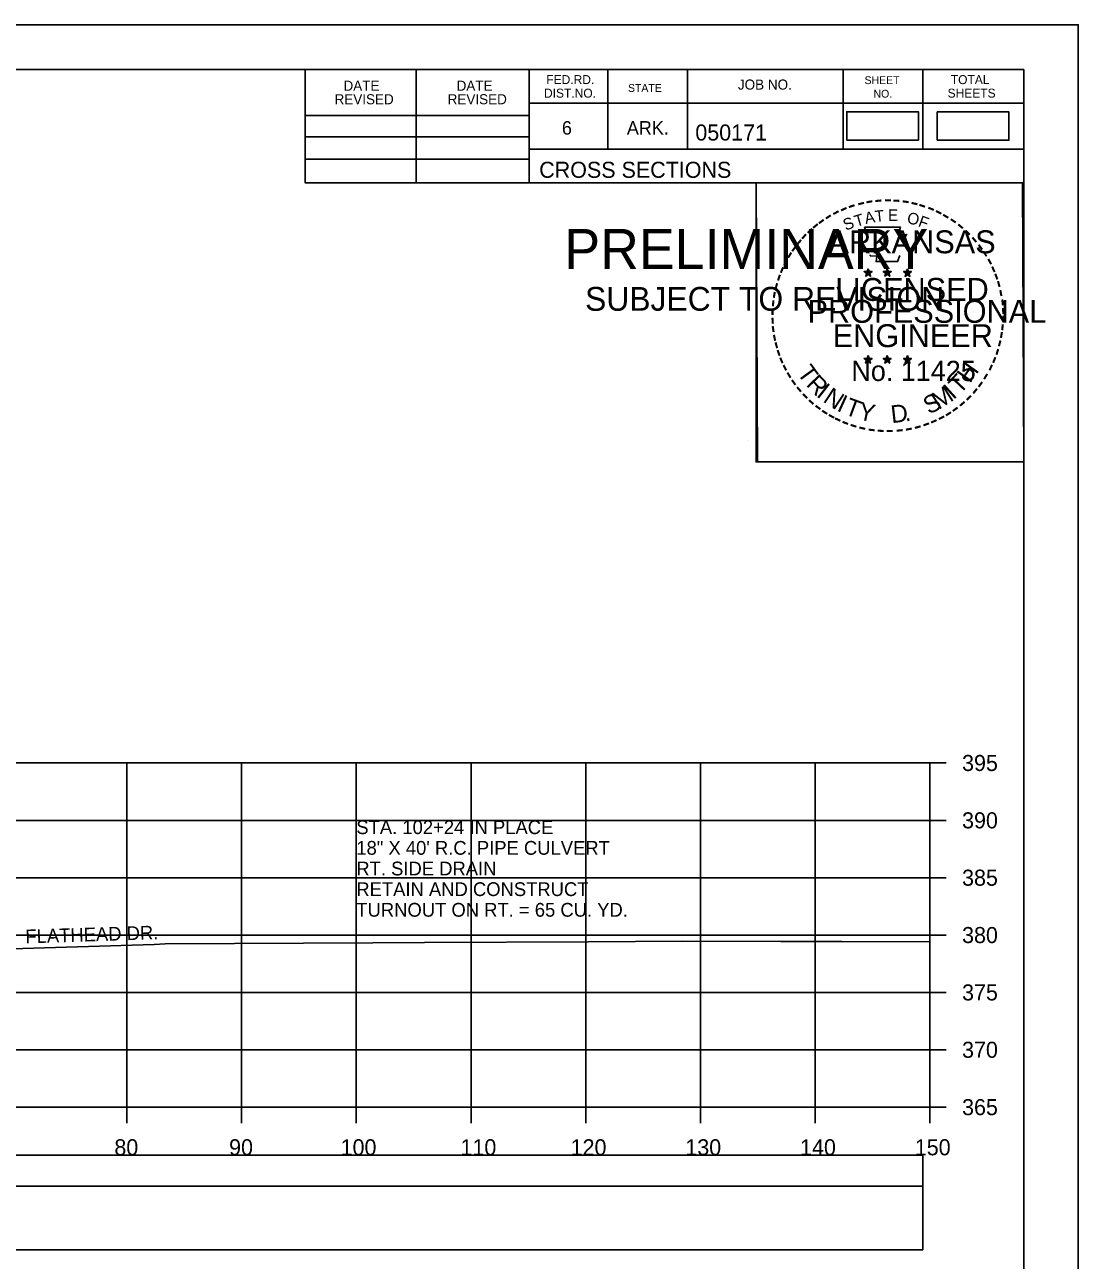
# Model space of a CAD drawing. Extents: x -37291014 to -37290680, y -936053 to -933067.
# Drawn here: x -37290772 to -37290680.2, y -935521 to -935413.3 of the extents above; entities that cross this region are included whole.
import ezdxf

# ---------------------------------------------------------------- set-up
doc = ezdxf.new("R2010")
doc.units = 0
for name, color, linetype in [('Default', 7, 'Continuous'), ('R_Axis', 7, 'Continuous'), ('R_Axis Annot', 7, 'Continuous'), ('R_Border', 7, 'Continuous'), ('R_Border PE', 7, 'Continuous'), ('R_Border Prem', 7, 'Continuous'), ('R_Exist Surface', 7, 'Continuous'), ('R_Grid', 7, 'Continuous'), ('R_No Plot', 7, 'Continuous'), ('R_Water Annot', 7, 'Continuous'), ('R_Xsect Elev', 7, 'Continuous')]:
    doc.layers.add(name, color=color, linetype=linetype)

msp = doc.modelspace()

# ---------------------------------------------------------------- linework, layer by layer
at = {"layer": 'Default'}
for points in [[(-37290700.35, -935423.36), (-37290694.1, -935423.36), (-37290694.1, -935420.88), (-37290700.35, -935420.88)], [(-37290692.46, -935423.36), (-37290686.21, -935423.36), (-37290686.21, -935420.89), (-37290692.46, -935420.89)], [(-37290992.48, -935514.55), (-37290693.72, -935514.55), (-37290693.72, -935511.85), (-37290992.48, -935511.85)], [(-37290992.48, -935520.08), (-37290693.72, -935520.08), (-37290693.72, -935514.55), (-37290992.48, -935514.55)]]:
    msp.add_lwpolyline(points, close=True, dxfattribs=at)
at = {"layer": 'R_Axis'}
for p, q in [((-37290693.1, -935507.65), (-37290693.1, -935477.65)), ((-37290691.7, -935477.65), (-37290693.1, -935477.65)), ((-37290691.7, -935482.65), (-37290693.1, -935482.65)), ((-37290691.7, -935487.65), (-37290693.1, -935487.65)), ((-37290691.7, -935492.65), (-37290693.1, -935492.65)), ((-37290691.7, -935497.65), (-37290693.1, -935497.65)), ((-37290691.7, -935502.65), (-37290693.1, -935502.65)), ((-37290993.1, -935507.65), (-37290693.1, -935507.65)), ((-37290763.1, -935509.05), (-37290763.1, -935507.65)), ((-37290753.1, -935509.05), (-37290753.1, -935507.65)), ((-37290743.1, -935509.05), (-37290743.1, -935507.65)), ((-37290733.1, -935509.05), (-37290733.1, -935507.65)), ((-37290723.1, -935509.05), (-37290723.1, -935507.65)), ((-37290713.1, -935509.05), (-37290713.1, -935507.65)), ((-37290703.1, -935509.05), (-37290703.1, -935507.65)), ((-37290693.1, -935509.05), (-37290693.1, -935507.65)), ((-37290691.7, -935507.65), (-37290693.1, -935507.65))]:
    msp.add_line(p, q, dxfattribs=at)
at = {"layer": 'R_Border'}
for p, q in [((-37291001.1, -935417.19), (-37290684.92, -935417.19)), ((-37290747.56, -935427.07), (-37290747.56, -935417.19)), ((-37290737.88, -935427.07), (-37290737.88, -935417.19)), ((-37290728.02, -935417.19), (-37290728.02, -935427.07)), ((-37290721.18, -935417.19), (-37290721.18, -935424.13)), ((-37290714.24, -935417.19), (-37290714.24, -935424.13)), ((-37290700.66, -935417.19), (-37290700.66, -935424.13)), ((-37290693.72, -935417.19), (-37290693.72, -935424.13)), ((-37290684.92, -935622.65), (-37290684.92, -935417.19)), ((-37290684.92, -935420.13), (-37290728.02, -935420.13)), ((-37290684.92, -935420.11), (-37290684.92, -935420.11)), ((-37290747.56, -935421.21), (-37290728.02, -935421.21)), ((-37290747.56, -935423.07), (-37290728.02, -935423.07)), ((-37290684.92, -935424.13), (-37290728.02, -935424.13)), ((-37290725.06, -935424.13), (-37290684.92, -935424.13)), ((-37290747.56, -935425.01), (-37290728.02, -935425.01)), ((-37290684.92, -935427.07), (-37290747.56, -935427.07))]:
    msp.add_line(p, q, dxfattribs=at)
at = {"layer": 'R_Border PE'}
for p, q in [((-37290698.84, -935434.81), (-37290698.49, -935434.92)), ((-37290698.84, -935434.81), (-37290698.58, -935434.86)), ((-37290698.84, -935434.81), (-37290698.6, -935434.93)), ((-37290698.7, -935435.22), (-37290698.49, -935434.92)), ((-37290698.7, -935435.22), (-37290698.58, -935434.98)), ((-37290698.49, -935434.56), (-37290698.53, -935434.81)), ((-37290698.49, -935434.92), (-37290698.49, -935434.56)), ((-37290698.49, -935434.56), (-37290698.44, -935434.81)), ((-37290698.14, -935434.81), (-37290698.49, -935434.92)), ((-37290698.27, -935435.22), (-37290698.49, -935434.92)), ((-37290698.14, -935434.81), (-37290698.43, -935434.86)), ((-37290698.27, -935435.22), (-37290698.41, -935434.93)), ((-37290698.14, -935434.81), (-37290698.34, -935434.91)), ((-37290697.17, -935434.81), (-37290696.82, -935434.92)), ((-37290697.17, -935434.81), (-37290696.91, -935434.86)), ((-37290697.17, -935434.81), (-37290696.93, -935434.93)), ((-37290697.03, -935435.22), (-37290696.82, -935434.92)), ((-37290697.03, -935435.22), (-37290696.91, -935434.98)), ((-37290696.82, -935434.56), (-37290696.86, -935434.81)), ((-37290696.82, -935434.92), (-37290696.82, -935434.56)), ((-37290696.82, -935434.56), (-37290696.77, -935434.81)), ((-37290696.47, -935434.81), (-37290696.82, -935434.92)), ((-37290696.6, -935435.22), (-37290696.82, -935434.92)), ((-37290696.47, -935434.81), (-37290696.76, -935434.86)), ((-37290696.6, -935435.22), (-37290696.74, -935434.93)), ((-37290696.47, -935434.81), (-37290696.67, -935434.91)), ((-37290695.4, -935434.82), (-37290695.05, -935434.94)), ((-37290695.4, -935434.82), (-37290695.15, -935434.87)), ((-37290695.4, -935434.82), (-37290695.17, -935434.95)), ((-37290695.27, -935435.23), (-37290695.05, -935434.94)), ((-37290695.27, -935435.23), (-37290695.14, -935434.99)), ((-37290695.05, -935434.57), (-37290695.09, -935434.82)), ((-37290695.05, -935434.94), (-37290695.05, -935434.57)), ((-37290695.05, -935434.57), (-37290695, -935434.82)), ((-37290694.71, -935434.82), (-37290695.05, -935434.94)), ((-37290694.84, -935435.23), (-37290695.05, -935434.94)), ((-37290694.71, -935434.82), (-37290694.99, -935434.87)), ((-37290694.84, -935435.23), (-37290694.98, -935434.94)), ((-37290694.71, -935434.82), (-37290694.91, -935434.93)), ((-37290698.7, -935435.22), (-37290698.49, -935435)), ((-37290698.27, -935435.22), (-37290698.49, -935435.01)), ((-37290697.03, -935435.22), (-37290696.82, -935435)), ((-37290696.6, -935435.22), (-37290696.82, -935435.01)), ((-37290695.27, -935435.23), (-37290695.06, -935435.02)), ((-37290694.84, -935435.23), (-37290695.06, -935435.02)), ((-37290698.84, -935442.39), (-37290698.49, -935442.5)), ((-37290698.84, -935442.39), (-37290698.59, -935442.43)), ((-37290698.84, -935442.39), (-37290698.6, -935442.51)), ((-37290698.71, -935442.79), (-37290698.49, -935442.5)), ((-37290698.49, -935442.13), (-37290698.53, -935442.38)), ((-37290698.49, -935442.5), (-37290698.49, -935442.13)), ((-37290698.49, -935442.13), (-37290698.44, -935442.38)), ((-37290698.14, -935442.39), (-37290698.49, -935442.5)), ((-37290698.28, -935442.79), (-37290698.49, -935442.5)), ((-37290698.14, -935442.39), (-37290698.43, -935442.43)), ((-37290698.28, -935442.79), (-37290698.42, -935442.5)), ((-37290698.14, -935442.39), (-37290698.35, -935442.49)), ((-37290697.17, -935442.39), (-37290696.82, -935442.5)), ((-37290697.17, -935442.39), (-37290696.92, -935442.43)), ((-37290697.17, -935442.39), (-37290696.93, -935442.51)), ((-37290697.04, -935442.79), (-37290696.82, -935442.5)), ((-37290696.82, -935442.13), (-37290696.86, -935442.38)), ((-37290696.82, -935442.5), (-37290696.82, -935442.13)), ((-37290696.82, -935442.13), (-37290696.77, -935442.38)), ((-37290696.48, -935442.39), (-37290696.82, -935442.5)), ((-37290696.61, -935442.79), (-37290696.82, -935442.5)), ((-37290696.48, -935442.39), (-37290696.76, -935442.43)), ((-37290696.61, -935442.79), (-37290696.75, -935442.5)), ((-37290696.48, -935442.39), (-37290696.68, -935442.49)), ((-37290695.4, -935442.4), (-37290695.06, -935442.51)), ((-37290695.4, -935442.4), (-37290695.15, -935442.44)), ((-37290695.4, -935442.4), (-37290695.17, -935442.52)), ((-37290695.27, -935442.8), (-37290695.06, -935442.51)), ((-37290695.06, -935442.14), (-37290695.1, -935442.39)), ((-37290695.06, -935442.51), (-37290695.06, -935442.14)), ((-37290695.06, -935442.14), (-37290695.01, -935442.39)), ((-37290694.71, -935442.4), (-37290695.06, -935442.51)), ((-37290694.84, -935442.8), (-37290695.06, -935442.51)), ((-37290694.71, -935442.4), (-37290694.99, -935442.44)), ((-37290694.84, -935442.8), (-37290694.98, -935442.51)), ((-37290694.71, -935442.4), (-37290694.91, -935442.5)), ((-37290698.71, -935442.79), (-37290698.58, -935442.55)), ((-37290698.71, -935442.79), (-37290698.49, -935442.58)), ((-37290698.28, -935442.79), (-37290698.49, -935442.58)), ((-37290697.04, -935442.79), (-37290696.91, -935442.55)), ((-37290697.04, -935442.79), (-37290696.82, -935442.58)), ((-37290696.61, -935442.79), (-37290696.82, -935442.58)), ((-37290695.27, -935442.8), (-37290695.15, -935442.56)), ((-37290695.27, -935442.8), (-37290695.06, -935442.59)), ((-37290694.84, -935442.8), (-37290695.06, -935442.59))]:
    msp.add_line(p, q, dxfattribs=at)
for points in [[(-37290698.8, -935430.93), (-37290698.53, -935431.76)], [(-37290695.28, -935431.86), (-37290695.14, -935431.57), (-37290695.83, -935431.6), (-37290695.68, -935430.93), (-37290698.8, -935430.93)], [(-37290698.3, -935433.36), (-37290698.3, -935433.44), (-37290697.74, -935433.46), (-37290697.79, -935433.94), (-37290695.92, -935433.94), (-37290695.72, -935433.4)], [(-37290698.49, -935434.56), (-37290698.27, -935435.22), (-37290698.84, -935434.81), (-37290698.14, -935434.81), (-37290698.7, -935435.22), (-37290698.49, -935434.56)], [(-37290696.82, -935434.56), (-37290696.6, -935435.22), (-37290697.17, -935434.81), (-37290696.47, -935434.81), (-37290697.03, -935435.22), (-37290696.82, -935434.56)], [(-37290695.05, -935434.57), (-37290694.84, -935435.23), (-37290695.4, -935434.82), (-37290694.71, -935434.82), (-37290695.27, -935435.23), (-37290695.05, -935434.57)], [(-37290698.49, -935442.13), (-37290698.28, -935442.79), (-37290698.84, -935442.39), (-37290698.14, -935442.39), (-37290698.71, -935442.79), (-37290698.49, -935442.13)], [(-37290696.82, -935442.13), (-37290696.61, -935442.79), (-37290697.17, -935442.39), (-37290696.48, -935442.39), (-37290697.04, -935442.79), (-37290696.82, -935442.13)], [(-37290695.06, -935442.14), (-37290694.84, -935442.8), (-37290695.4, -935442.4), (-37290694.71, -935442.4), (-37290695.27, -935442.8), (-37290695.06, -935442.14)]]:
    msp.add_lwpolyline(points, dxfattribs=at)
for centre, radius in [((-37290698.49, -935434.92), 0.172), ((-37290698.49, -935434.92), 0.145), ((-37290698.49, -935434.92), 0.116), ((-37290698.49, -935434.92), 0.0991), ((-37290698.49, -935434.92), 0.0747), ((-37290698.49, -935434.92), 0.0495), ((-37290698.49, -935434.92), 0.0296), ((-37290696.82, -935434.92), 0.172), ((-37290696.82, -935434.92), 0.145), ((-37290696.82, -935434.92), 0.116), ((-37290696.82, -935434.92), 0.0991), ((-37290696.82, -935434.92), 0.0747), ((-37290696.82, -935434.92), 0.0495), ((-37290696.82, -935434.92), 0.0296), ((-37290695.05, -935434.94), 0.172), ((-37290695.05, -935434.94), 0.145), ((-37290695.05, -935434.94), 0.116), ((-37290695.05, -935434.94), 0.0991), ((-37290695.05, -935434.94), 0.0747), ((-37290695.05, -935434.94), 0.0495), ((-37290695.05, -935434.94), 0.0296), ((-37290698.49, -935442.5), 0.172), ((-37290698.49, -935442.5), 0.145), ((-37290698.49, -935442.5), 0.116), ((-37290698.49, -935442.5), 0.0991), ((-37290698.49, -935442.5), 0.0747), ((-37290698.49, -935442.5), 0.0495), ((-37290698.49, -935442.5), 0.0296), ((-37290696.82, -935442.5), 0.172), ((-37290696.82, -935442.5), 0.145), ((-37290696.82, -935442.5), 0.116), ((-37290696.82, -935442.5), 0.0991), ((-37290696.82, -935442.5), 0.0747), ((-37290696.82, -935442.5), 0.0495), ((-37290696.82, -935442.5), 0.0296), ((-37290695.06, -935442.51), 0.172), ((-37290695.06, -935442.51), 0.145), ((-37290695.06, -935442.51), 0.116), ((-37290695.06, -935442.51), 0.0991), ((-37290695.06, -935442.51), 0.0747), ((-37290695.06, -935442.51), 0.0495), ((-37290695.06, -935442.51), 0.0296)]:
    msp.add_circle(centre, radius, dxfattribs=at)
at = {"layer": 'R_Exist Surface'}
msp.add_lwpolyline([(-37290774.08, -935493.88), (-37290760.71, -935493.46), (-37290759.75, -935493.42), (-37290741.66, -935493.34), (-37290737.15, -935493.31), (-37290722.9, -935493.24), (-37290714.65, -935493.17), (-37290706.09, -935493.2), (-37290700.79, -935493.2), (-37290693.1, -935493.24)], dxfattribs=at)
at = {"layer": 'R_Grid'}
for p, q in [((-37290993.1, -935477.65), (-37290693.1, -935477.65)), ((-37290763.1, -935507.65), (-37290763.1, -935477.65)), ((-37290753.1, -935507.65), (-37290753.1, -935477.65)), ((-37290743.1, -935507.65), (-37290743.1, -935477.65)), ((-37290733.1, -935507.65), (-37290733.1, -935477.65)), ((-37290723.1, -935507.65), (-37290723.1, -935477.65)), ((-37290713.1, -935507.65), (-37290713.1, -935477.65)), ((-37290703.1, -935507.65), (-37290703.1, -935477.65)), ((-37290693.1, -935507.65), (-37290693.1, -935477.65)), ((-37290993.1, -935482.65), (-37290693.1, -935482.65)), ((-37290993.1, -935487.65), (-37290693.1, -935487.65)), ((-37290993.1, -935492.65), (-37290693.1, -935492.65)), ((-37290993.1, -935497.65), (-37290693.1, -935497.65)), ((-37290993.1, -935502.65), (-37290693.1, -935502.65)), ((-37290993.1, -935507.65), (-37290693.1, -935507.65))]:
    msp.add_line(p, q, dxfattribs=at)
at = {"layer": 'R_No Plot'}
for p, q in [((-37291013.5, -935413.29), (-37290680.17, -935413.29)), ((-37290708.89, -935449.52), (-37290708.89, -935449.52))]:
    msp.add_line(p, q, dxfattribs=at)
for points in [[(-37291013.51, -935413.29), (-37290680.17, -935413.29), (-37290680.17, -935626.63), (-37291013.51, -935626.63)], [(-37290767.18, -935417.19), (-37290747.56, -935417.19), (-37290747.56, -935427.07), (-37290731.45, -935427.07), (-37290708.25, -935427.07), (-37290708.25, -935451.4), (-37290684.92, -935451.4), (-37290684.92, -935622.65), (-37291001.1, -935622.65), (-37291001.1, -935417.19)], [(-37290708.25, -935427.07), (-37290685.04, -935427.07), (-37290684.92, -935451.4), (-37290708.13, -935451.4)]]:
    msp.add_lwpolyline(points, close=True, dxfattribs=at)

# ---------------------------------------------------------------- texts
at = {"layer": 'R_Axis Annot'}
for s, p in [('395', (-37290690.3, -935478.35)), ('390', (-37290690.3, -935483.35)), ('385', (-37290690.3, -935488.35)), ('380', (-37290690.3, -935493.35)), ('375', (-37290690.3, -935498.35)), ('370', (-37290690.3, -935503.35)), ('365', (-37290690.3, -935508.35)), ('80', (-37290764.19, -935511.85)), ('90', (-37290754.19, -935511.85)), ('100', (-37290744.47, -935511.85)), ('110', (-37290734.02, -935511.85)), ('120', (-37290724.42, -935511.85)), ('130', (-37290714.42, -935511.85)), ('140', (-37290704.42, -935511.85)), ('150', (-37290694.42, -935511.85))]:
    msp.add_text(s, height=1.4, dxfattribs=at).set_placement(p)
at = {"layer": 'R_Border'}
for s, height, p in [('FED.RD.', 0.782, (-37290726.54, -935418.47)), ('TOTAL', 0.782, (-37290691.28, -935418.47)), ('DATE', 0.879, (-37290744.22, -935419.05)), ('DATE', 0.879, (-37290734.36, -935419.05)), ('STATE', 0.684, (-37290719.42, -935419.15)), ('JOB NO.', 0.879, (-37290709.84, -935418.95)), ('SHEET', 0.684, (-37290698.8, -935418.47)), ('REVISED', 0.879, (-37290745, -935420.23)), ('REVISED', 0.879, (-37290735.14, -935420.23)), ('DIST.NO.', 0.782, (-37290726.74, -935419.65)), ('NO.', 0.684, (-37290698.02, -935419.65)), ('SHEETS', 0.782, (-37290691.56, -935419.65)), ('6', 1.17, (-37290725.18, -935422.87)), ('ARK.', 1.172, (-37290719.52, -935422.87)), ('050171', 1.4, (-37290713.55, -935423.39)), ('CROSS SECTIONS', 1.4, (-37290727.16, -935426.64))]:
    msp.add_text(s, height=height, dxfattribs=at).set_placement(p)
at = {"layer": 'R_Border PE'}
for s, height, rotation, p in [('-', 1.6, 5.8968, (-37290697.89, -935429.29)), ('-', 1.6, 0.1862, (-37290697.12, -935429.22)), ('-', 1.6, 357.743, (-37290696.4, -935429.24)), ('-', 1.6, 28.7918, (-37290701.31, -935430.39)), ('-', 1.6, 24.3072, (-37290700.68, -935430.08)), ('-', 1.6, 19.1761, (-37290700.05, -935429.81)), ('-', 1.6, 13.6302, (-37290699.3, -935429.57)), ('A', 1, 11.2132, (-37290698.7, -935430.67)), ('-', 1.6, 10.2193, (-37290698.62, -935429.4)), ('T', 1, 6.0228, (-37290697.85, -935430.51)), ('E', 1, 0.8323, (-37290696.75, -935430.4)), ('-', 1.6, 352.1617, (-37290695.65, -935429.29)), ('-', 1.6, 347.2049, (-37290694.93, -935429.41)), ('-', 1.6, 342.3362, (-37290694.3, -935429.56)), ('-', 1.6, 337.8551, (-37290693.56, -935429.78)), ('-', 1.6, 334.1211, (-37290692.93, -935430.05)), ('-', 1.6, 38.9507, (-37290702.97, -935431.54)), ('-', 1.6, 36.2317, (-37290702.49, -935431.16)), ('-', 1.6, 34.0636, (-37290701.91, -935430.76)), ('S', 1, 21.594, (-37290700.44, -935431.26)), ('T', 1, 16.4036, (-37290699.53, -935430.93)), ('O', 1, 350.4515, (-37290695.14, -935430.61)), ('F', 1, 340.0707, (-37290694.19, -935430.84)), ('-', 1.6, 329.6409, (-37290692.35, -935430.34)), ('-', 1.6, 325.8627, (-37290691.71, -935430.7)), ('-', 1.6, 320.5297, (-37290691.1, -935431.12)), ('-', 1.6, 48.4231, (-37290703.85, -935432.43)), ('-', 1.6, 42.9622, (-37290703.4, -935431.95)), ('-', 1.6, 315.5786, (-37290690.5, -935431.61)), ('-', 1.6, 54.2325, (-37290704.66, -935433.48)), ('-', 1.6, 50.6142, (-37290704.25, -935432.92)), ('-', 1.6, 309.8797, (-37290689.93, -935432.16)), ('-', 1.6, 306.6522, (-37290689.41, -935432.76)), ('-', 1.6, 62.8713, (-37290705.3, -935434.63)), ('-', 1.6, 58.0706, (-37290704.99, -935434.01)), ('-', 1.4, 303.6753, (-37290688.92, -935433.33)), ('-', 1.6, 299.6684, (-37290688.6, -935433.94)), ('-', 1.6, 67.7743, (-37290705.56, -935435.24)), ('-', 1.6, 294.6628, (-37290688.28, -935434.55)), ('-', 1.6, 290.5728, (-37290688.02, -935435.13)), ('-', 1.6, 75.461, (-37290705.98, -935436.58)), ('-', 1.6, 72.3945, (-37290705.78, -935435.87)), ('-', 1.6, 285.1233, (-37290687.79, -935435.71)), ('-', 1.6, 81.2013, (-37290706.11, -935437.29)), ('-', 1.6, 280.5493, (-37290687.59, -935436.45)), ('-', 1.6, 89.0622, (-37290706.21, -935438.69)), ('-', 1.6, 85.1863, (-37290706.18, -935437.98)), ('-', 1.6, 276.5962, (-37290687.42, -935437.22)), ('-', 1.6, 274.3301, (-37290687.36, -935437.94)), ('-', 1.6, 94.1959, (-37290706.17, -935439.41)), ('-', 1.6, 269.9407, (-37290687.33, -935438.57)), ('-', 1.6, 98.9479, (-37290706.1, -935440.08)), ('-', 1.6, 101.7149, (-37290705.97, -935440.81)), ('-', 1.6, 260.9953, (-37290687.42, -935439.89)), ('-', 1.6, 263.5172, (-37290687.35, -935439.24)), ('-', 1.6, 105.4578, (-37290705.8, -935441.41)), ('-', 1.6, 255.7626, (-37290687.53, -935440.57)), ('-', 1.6, 109.0874, (-37290705.59, -935442.04)), ('-', 1.6, 114.0643, (-37290705.34, -935442.63)), ('-', 1.6, 247.8887, (-37290687.93, -935441.96)), ('-', 1.6, 252.8681, (-37290687.71, -935441.29)), ('-', 1.6, 115.7289, (-37290705.03, -935443.25)), ('-', 1.6, 120.4471, (-37290704.67, -935443.84)), ('T', 1.54, 306.0406, (-37290704.73, -935443.66)), ('H', 1.54, 54.6088, (-37290689.61, -935444.62)), ('-', 1.6, 244.6197, (-37290688.2, -935442.59)), ('-', 1.6, 125.8934, (-37290704.27, -935444.4)), ('R', 1.54, 314.005, (-37290703.97, -935444.71)), ('I', 1.54, 321.9694, (-37290703.07, -935445.64)), ('I', 1.54, 42.1136, (-37290691.06, -935446.04)), ('T', 1.54, 46.6444, (-37290690.5, -935445.57)), ('-', 1.6, 233.8452, (-37290688.99, -935444)), ('-', 1.6, 239.0712, (-37290688.59, -935443.34)), ('-', 1.6, 130.7181, (-37290703.81, -935444.95)), ('-', 1.6, 134.2238, (-37290703.29, -935445.49)), ('N', 1.54, 326.5002, (-37290702.5, -935446.11)), ('I', 1.54, 335.3603, (-37290701.29, -935446.9)), ('S', 1.54, 26.9312, (-37290693.19, -935447.3)), ('M', 1.54, 32.6563, (-37290692.35, -935446.89)), ('-', 1.6, 225.7653, (-37290689.9, -935445.13)), ('-', 1.6, 231.2538, (-37290689.42, -935444.56)), ('-', 1.6, 138.9338, (-37290702.77, -935445.96)), ('-', 1.6, 144.6463, (-37290702.21, -935446.36)), ('T', 1.54, 339.8912, (-37290700.63, -935447.22)), ('Y', 1.54, 347.8556, (-37290699.42, -935447.67)), ('D', 1.54, 6.3969, (-37290696.43, -935448.03)), ('-', 1.6, 215.7363, (-37290690.97, -935446.11)), ('-', 1.6, 221.0851, (-37290690.42, -935445.64)), ('-', 1.6, 148.0898, (-37290701.65, -935446.74)), ('-', 1.6, 151.5704, (-37290701.07, -935447.06)), ('-', 1.6, 154.6002, (-37290700.55, -935447.31)), ('-', 1.6, 158.5612, (-37290699.92, -935447.56)), ('.', 1.54, 13.7642, (-37290695.24, -935447.9)), ('-', 1.6, 204.2516, (-37290692.69, -935447.16)), ('-', 1.6, 207.3568, (-37290692.06, -935446.84)), ('-', 1.6, 212.2491, (-37290691.51, -935446.5)), ('-', 1.6, 162.7983, (-37290699.24, -935447.77)), ('-', 1.6, 167.5555, (-37290698.52, -935447.94)), ('-', 1.6, 173.1155, (-37290697.75, -935448.05)), ('-', 1.6, 176.5183, (-37290697, -935448.1)), ('-', 1.6, 181.5918, (-37290696.26, -935448.08)), ('-', 1.6, 185.8167, (-37290695.45, -935448.01)), ('-', 1.6, 191.2858, (-37290694.71, -935447.87)), ('-', 1.6, 195.4743, (-37290693.98, -935447.68)), ('-', 1.6, 200.7184, (-37290693.31, -935447.43))]:
    msp.add_text(s, height=height, rotation=rotation, dxfattribs=at).set_placement(p)
for s, height, p in [('ARKANSAS', 2, (-37290701.94, -935433.22)), ('DWB', 0.01, (-37290698.5, -935434.93)), ('DWB', 0.01, (-37290696.83, -935434.93)), ('DWB', 0.01, (-37290695.07, -935434.94)), ('LICENSED', 2, (-37290701.35, -935437.37)), ('PROFESSIONAL', 2, (-37290703.77, -935439.28)), ('ENGINEER', 2, (-37290701.58, -935441.4)), ('DWB', 0.01, (-37290698.5, -935442.5)), ('DWB', 0.01, (-37290696.84, -935442.5)), ('DWB', 0.01, (-37290695.07, -935442.51)), ('No. 11425', 1.757, (-37290699.95, -935444.35))]:
    msp.add_text(s, height=height, dxfattribs=at).set_placement(p)
at = {"layer": 'R_Border Prem'}
for s, height, p in [('PRELIMINARY', 3.5, (-37290724.97, -935434.6)), ('DWB', 0.01, (-37290724.22, -935432.76)), ('SUBJECT TO REVISION', 2.0751, (-37290723.16, -935438.23))]:
    msp.add_text(s, height=height, dxfattribs=at).set_placement(p)
at = {"layer": 'R_Water Annot'}
for s, p in [('STA. 102+24 IN PLACE', (-37290743.1, -935483.85)), ('18" X 40\' R.C. PIPE CULVERT', (-37290743.1, -935485.65)), ('RT. SIDE DRAIN', (-37290743.1, -935487.45)), ('RETAIN AND CONSTRUCT', (-37290743.1, -935489.25)), ('TURNOUT ON RT. = 65 CU. YD.', (-37290743.1, -935491.05))]:
    msp.add_text(s, height=1.2, dxfattribs=at).set_placement(p)
at = {"layer": 'R_Xsect Elev'}
msp.add_text('FLATHEAD DR.', height=1.2, rotation=1.8162, dxfattribs=at).set_placement((-37290771.93, -935493.38))

doc.saveas('drawing.dxf')
